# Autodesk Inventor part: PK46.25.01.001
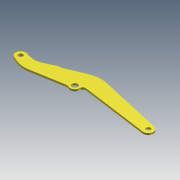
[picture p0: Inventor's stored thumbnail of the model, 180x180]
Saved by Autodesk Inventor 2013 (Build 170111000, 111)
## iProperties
Created: 2005-04
Part Number: PK46.25.01.001
Material: Steel, Mild
Document SubType Name: Modeling
Designer: salex
Manufacturer: Standard
Standards Organization: Custom
Density: 7.86 g/cm^3
d33: 655.000 mm
Author: salex
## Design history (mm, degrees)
sketch "Эскиз1"
  geometry: L1 (0, 0)-(2780, 0); L2 (33.051, 104.917)-(105.364, 82.138); L3 (396.783, 102.16)-(635, 215); L4 (635, 215)-(645.867, 206.69); L5 (665.631, 204.083)-(1099.06, 382.554); L6 (1460.537, 412.814)-(2804.388, 107.262); L7 (-42.453, -101.478)-(70.783, -148.85); L8 (348.39, -180.372)-(1036.629, -62.165); L9 (2764.842, -108.951)-(1339.646, 89.332); L10 (255, 35)-(873.631, 289.73); L11 (635, 215)-(655, 199.706); C1 r 47.5 at (0, 0); C2 r 47.5 at (2780, 0); C3 r 62.5 at (1160, 20); A1 r 110 centre (0, 0) between (33.051, 104.917) and (-42.453, -101.478); A2 r 100 centre (1160, 20) between (1120.808, -72) and (1260, 20); A3 r 110 centre (2780, 0) between (2764.842, -108.951) and (2804.388, 107.262); A4 r 20 centre (658.016, 222.577) between (645.867, 206.69) and (665.631, 204.083); A5 r 150 centre (1062.02, -210) between (1120.808, -72) and (1036.629, -62.165); A6 r 70 centre (1330, 20) between (1339.646, 89.332) and (1260, 20); A7 r 400 centre (225.548, 463.655) between (105.364, 82.138) and (396.783, 102.16); A8 r 500 centre (263.752, 312.412) between (70.783, -148.85) and (348.39, -180.372); A9 r 600 centre (1327.51, -172.253) between (1460.537, 412.814) and (1099.06, 382.554); 2 further points
  constraints: 22 end point, 19 point on circle, 17 tangent, 12 centre point, 8 point on line, 5 coincident, 2 collinear, 2 equal radius, 1 horizontal, 1 other
  dimensions: "d0" = 2780 distance of C2.centre C1.centre; "d1" = 95 diameter of C1; "d2" = 125 diameter of C3; "d3" = 100 radius of A2; "d4" = 110 radius of A1; "d5" = 255 horizontal distance of L10.start A1.centre; "d6" = 35 distance from line of L10.start L1; "d7" = 205 horizontal distance of point (205, -205) C1.centre; "d8" = 205 distance from line of point (205, -205) L1; "d9" = 1620 horizontal distance of C2.centre C3.centre; "d10" = 20 distance from line of L1 C3.centre; "d11" = 150 radius of A5; "d13" = 70 radius of A6; "d14" = 170 distance of A6.centre C3.centre; "d15" = 455 distance from line of point (1275, 455) L1; "d16" = 1275 horizontal distance of point (1275, 455) C1.centre; "d17" = 635 horizontal distance of L3.end C1.centre; "d18" = 215 distance from line of L3.end L1; "d19" = 400 radius of A7; "d25" = 500 radius of A8; "d27" = 230 vertical distance of A5.centre C3.centre; "d28" = 600 radius of A9; "d33" = 655 horizontal distance of C1.centre L11.end; "d34" = 20 radius of A4
extrude "Выдавливание1" new body sketch "Эскиз1" taper "d30" = 0 deg; distance "Thickness" = 40
body "Solid1"
